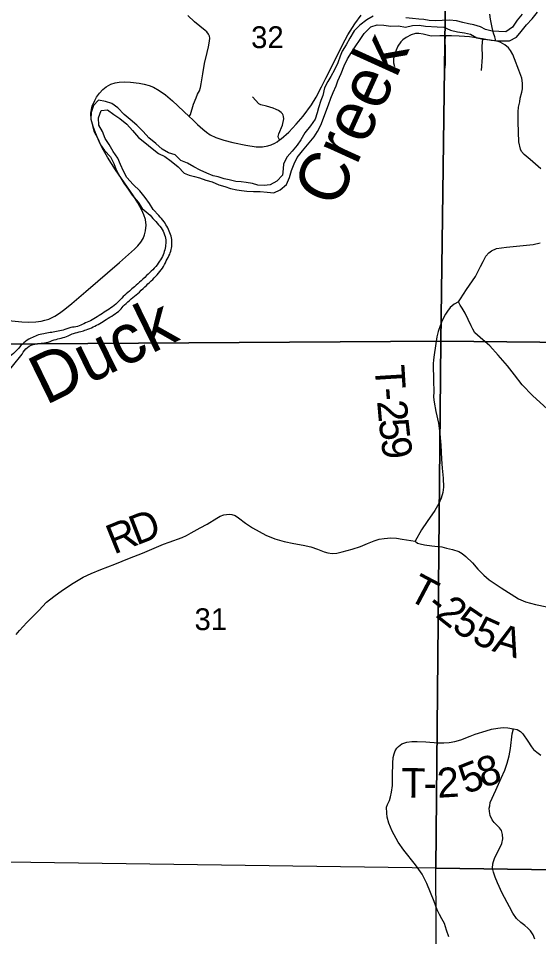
# Model space of a CAD drawing. Extents: x 0 to 34, y 0 to 22.
# Drawn here: x 6.533 to 7.529, y 17.691 to 19.45 of the extents above; entities that cross this region are included whole.
import ezdxf

# ---------------------------------------------------------------- set-up
doc = ezdxf.new("R2010")
doc.units = 0
for name, color, linetype in [('GM_X_Corporation', 7, 'Continuous'), ('GM_X_County_Road', 7, 'Continuous'), ('GM_X_Major_River', 7, 'Continuous'), ('GM_X_Major_River_Text', 7, 'Continuous'), ('GM_X_Section_Text', 7, 'Continuous'), ('GM_X_State_Route', 7, 'Continuous'), ('GM_X_Township_Road', 7, 'Continuous'), ('GM_X_Township_Road_Text', 7, 'Continuous')]:
    doc.layers.add(name, color=color, linetype=linetype)

msp = doc.modelspace()

# ---------------------------------------------------------------- linework, layer by layer
at = {"layer": 'GM_X_Corporation'}
for points in [[(7.3548, 19.8302), (7.3418, 18.8315), (6.4726, 18.8257), (6.4758, 19.3912), (6.4778, 19.8399)], [(8.3645, 19.8193), (8.353, 18.8213), (7.3418, 18.8315), (7.3548, 19.8302)], [(7.3418, 18.8315), (7.332, 17.8222), (6.4651, 17.8343), (6.4692, 18.391), (6.4726, 18.8257)], [(8.353, 18.8213), (8.3394, 17.8082), (7.332, 17.8222), (7.3418, 18.8315)], [(8.3394, 17.8082), (8.3265, 16.8592), (7.3376, 16.8759), (7.332, 17.8222)]]:
    msp.add_lwpolyline(points, close=True, dxfattribs=at)
at = {"layer": 'GM_X_County_Road'}
for points in [[(7.5332, 19.1614), (7.5129, 19.1793), (7.5011, 19.1892), (7.4959, 19.1947), (7.4939, 19.1994), (7.4912, 19.2136), (7.4896, 19.2512), (7.4899, 19.2707), (7.4906, 19.2797), (7.4926, 19.2898), (7.4936, 19.2971), (7.4965, 19.3081), (7.4983, 19.3146), (7.4981, 19.3257), (7.4969, 19.3355), (7.4912, 19.3508), (7.4827, 19.3724), (7.4795, 19.3808), (7.4753, 19.388), (7.4712, 19.3931), (7.4643, 19.3992), (7.4552, 19.4039), (7.4467, 19.4066), (7.4449, 19.4145), (7.4422, 19.4213), (7.4399, 19.4324), (7.4385, 19.4385), (7.4367, 19.4485), (7.4357, 19.4575)], [(7.5461, 18.7013), (7.517, 18.7276), (7.4975, 18.7477), (7.4824, 18.7671), (7.4695, 18.7842), (7.4517, 18.8049), (7.4358, 18.8224), (7.4265, 18.8301), (7.4171, 18.8384), (7.4119, 18.8431), (7.407, 18.8478), (7.4027, 18.8543), (7.3998, 18.861), (7.3943, 18.8729), (7.3885, 18.8851), (7.3823, 18.895), (7.379, 18.9006), (7.3756, 18.907), (7.3791, 18.9128), (7.391, 18.9306), (7.4082, 18.9553), (7.4179, 18.9745), (7.4226, 18.9843), (7.4278, 18.9943), (7.4337, 19.0008), (7.4388, 19.0045), (7.448, 19.0091), (7.4672, 19.0113), (7.5185, 19.0165), (7.5317, 19.0201)]]:
    msp.add_lwpolyline(points, dxfattribs=at)
at = {"layer": 'GM_X_Major_River'}
for points in [[(7.2123, 19.4537), (7.1999, 19.4467), (7.1867, 19.4367), (7.1759, 19.4256), (7.1673, 19.4119), (7.1603, 19.3993), (7.1532, 19.3871), (7.1492, 19.3772), (7.1444, 19.3646), (7.1381, 19.3512), (7.1314, 19.3383), (7.1255, 19.3287), (7.1192, 19.3165), (7.1159, 19.3021), (7.1122, 19.2926), (7.1075, 19.2785), (7.1053, 19.269), (7.1013, 19.2568), (7.0923, 19.2438), (7.0815, 19.2304), (7.0741, 19.2174), (7.067, 19.2071), (7.0569, 19.1956), (7.0476, 19.1846), (7.0409, 19.1712), (7.0403, 19.1613)], [(7.1057, 19.233), (7.112, 19.2452), (7.1172, 19.2585), (7.1216, 19.2707), (7.1267, 19.284), (7.1315, 19.2966), (7.1359, 19.3076), (7.1415, 19.3206), (7.1444, 19.3301), (7.1507, 19.3442), (7.1566, 19.3586), (7.1632, 19.3724), (7.171, 19.3842), (7.1788, 19.3972), (7.1859, 19.4075), (7.1949, 19.4205), (7.208, 19.4335), (7.2197, 19.4374), (7.2329, 19.4364), (7.2462, 19.4347), (7.2609, 19.4352), (7.2742, 19.4327), (7.2878, 19.4363), (7.3003, 19.4368), (7.3124, 19.4346), (7.3344, 19.4333), (7.3472, 19.4331), (7.3605, 19.4272), (7.3738, 19.4239), (7.3871, 19.4218), (7.3988, 19.4196), (7.4107, 19.4125), (7.4228, 19.41), (7.4361, 19.4083), (7.4482, 19.4065), (7.4603, 19.407), (7.4732, 19.4064), (7.4867, 19.4137), (7.4957, 19.4244), (7.5057, 19.4374), (7.5162, 19.4489), (7.527, 19.4619)], [(7.4972, 19.4578), (7.4875, 19.446), (7.4786, 19.4326), (7.4658, 19.4241), (7.4525, 19.4244), (7.44, 19.4254), (7.4271, 19.4286), (7.4176, 19.4335), (7.4051, 19.4375), (7.3948, 19.4393), (7.3838, 19.4418), (7.3717, 19.4451), (7.3584, 19.4461), (7.3444, 19.4456), (7.3316, 19.4451), (7.3191, 19.4457), (7.3092, 19.4475), (7.2994, 19.4485), (7.2873, 19.4492), (7.2748, 19.4509)], [(7.0403, 19.1613), (7.0389, 19.1496), (7.028, 19.1381), (7.0149, 19.1311), (7.0035, 19.1298), (6.9914, 19.1301), (6.9815, 19.1334), (6.969, 19.1352), (6.9596, 19.1366), (6.9497, 19.1376), (6.9368, 19.1405), (6.9273, 19.1423), (6.9156, 19.146), (6.9061, 19.1482), (6.8939, 19.1533), (6.881, 19.1593), (6.8688, 19.1652), (6.8566, 19.1723), (6.8444, 19.1778), (6.833, 19.1883), (6.8208, 19.1924), (6.8083, 19.1995), (6.796, 19.2103), (6.783, 19.2212), (6.7723, 19.2332), (6.7597, 19.2452), (6.7471, 19.2561), (6.7356, 19.2658), (6.7234, 19.2782), (6.7123, 19.2868), (6.6998, 19.2908), (6.6865, 19.293), (6.6768, 19.2826), (6.6728, 19.2697), (6.6718, 19.2575), (6.6749, 19.2447), (6.6785, 19.2326), (6.6854, 19.2198), (6.6905, 19.2073), (6.6978, 19.1964), (6.7093, 19.1848), (6.7158, 19.1719), (6.7205, 19.1595), (6.7271, 19.1466), (6.7348, 19.1342), (6.7432, 19.1229), (6.7509, 19.1109), (6.7624, 19.0977), (6.7701, 19.0857), (6.7856, 19.0726)], [(6.8019, 19.0722), (6.7911, 19.0837), (6.7844, 19.0949), (6.776, 19.107), (6.766, 19.1197), (6.753, 19.1317), (6.7411, 19.1449), (6.7342, 19.1573), (6.7287, 19.1698), (6.7237, 19.1819), (6.7145, 19.195), (6.7067, 19.2079), (6.6994, 19.2199), (6.694, 19.2328), (6.687, 19.2452), (6.6865, 19.2592), (6.6917, 19.2733), (6.7041, 19.2746), (6.716, 19.2656), (6.7274, 19.2581), (6.7411, 19.2473), (6.7519, 19.2349), (6.7634, 19.2217), (6.7752, 19.212), (6.7893, 19.2008), (6.8015, 19.191), (6.8137, 19.1855), (6.8259, 19.1765), (6.8393, 19.1653), (6.8508, 19.1533), (6.8603, 19.1492), (6.8701, 19.147), (6.8796, 19.1441), (6.8922, 19.14), (6.9039, 19.1368), (6.9169, 19.1312), (6.9286, 19.1279), (6.9389, 19.1242), (6.951, 19.1213), (6.9605, 19.1199), (6.9707, 19.1189), (6.9832, 19.1179), (6.9961, 19.118), (7.0093, 19.117), (7.0222, 19.1156), (7.0343, 19.1215), (7.0466, 19.1314), (7.0522, 19.1448), (7.0562, 19.1585), (7.061, 19.171), (7.0669, 19.1832), (7.077, 19.1962), (7.0994, 19.223), (7.1057, 19.233)]]:
    msp.add_lwpolyline(points, dxfattribs=at)
for points in [[(6.7856, 19.0726), (6.796, 19.0607), (6.8065, 19.0483), (6.8132, 19.0355), (6.8153, 19.0219), (6.814, 19.0097), (6.8104, 18.9971), (6.8034, 18.9845), (6.7934, 18.9714), (6.7815, 18.9602), (6.7684, 18.9474), (6.7553, 18.9358), (6.7456, 18.9272), (6.734, 18.9168), (6.7225, 18.9052), (6.7105, 18.8951), (6.6974, 18.8869), (6.6843, 18.8783), (6.6711, 18.8705), (6.6587, 18.865), (6.6463, 18.8598), (6.6334, 18.8577), (6.6187, 18.8529), (6.6059, 18.85), (6.5941, 18.8479), (6.5817, 18.8458), (6.5688, 18.8425), (6.5571, 18.8374), (6.5436, 18.8284), (6.5332, 18.8176), (6.5209, 18.8052), (6.5082, 18.7948), (6.4951, 18.7824), (6.4831, 18.7738), (6.4699, 18.7728), (6.4573, 18.776), (6.4436, 18.7781), (6.4306, 18.7832), (6.418, 18.7905), (6.4054, 18.796), (6.3927, 18.8042), (6.3812, 18.8112), (6.369, 18.8163), (6.3557, 18.8179), (6.3462, 18.8182), (6.3329, 18.8202), (6.3184, 18.8219), (6.304, 18.8246), (6.291, 18.829), (6.2792, 18.8307), (6.2671, 18.832), (6.2553, 18.8295), (6.2456, 18.8248), (6.2343, 18.8193), (6.2227, 18.8092), (6.2142, 18.7973), (6.2064, 18.7876), (6.1979, 18.7738), (6.1928, 18.7604), (6.1877, 18.7501), (6.1845, 18.7379), (6.1851, 18.7242), (6.188, 18.7117), (6.192, 18.6993), (6.1941, 18.6879), (6.1966, 18.6739), (6.1987, 18.6603), (6.2035, 18.6471), (6.2098, 18.6342), (6.2153, 18.6211), (6.2197, 18.6082), (6.2241, 18.5961), (6.2285, 18.5833), (6.2291, 18.5712), (6.2335, 18.5587), (6.2386, 18.5466), (6.2453, 18.5342), (6.2505, 18.5222), (6.2609, 18.5098), (6.2732, 18.4986), (6.2814, 18.4866), (6.2919, 18.4727), (6.2963, 18.4603), (6.2984, 18.4485), (6.302, 18.4372), (6.3011, 18.4231), (6.2968, 18.4102), (6.2909, 18.3975), (6.2813, 18.3856), (6.2693, 18.3759), (6.2566, 18.3669), (6.2434, 18.3595), (6.231, 18.3524), (6.2163, 18.3465), (6.2032, 18.3405), (6.1885, 18.3331), (6.1753, 18.3291)], [(6.2087, 18.3296), (6.2215, 18.3352), (6.2331, 18.3395), (6.2433, 18.3447), (6.255, 18.3502), (6.2685, 18.3569), (6.2809, 18.3624), (6.2932, 18.374), (6.3018, 18.3859), (6.3099, 18.3986), (6.3153, 18.4139), (6.3177, 18.4261), (6.319, 18.4386), (6.3177, 18.4489), (6.3133, 18.4625), (6.3071, 18.4738), (6.2996, 18.4858), (6.2926, 18.4978), (6.2826, 18.5071), (6.2718, 18.5183), (6.2606, 18.5299), (6.2554, 18.542), (6.2503, 18.5537), (6.2467, 18.5661), (6.2431, 18.5767), (6.2406, 18.5892), (6.2365, 18.6039), (6.2318, 18.6156), (6.2262, 18.6288), (6.2214, 18.6417), (6.2174, 18.6537), (6.2142, 18.6639), (6.2094, 18.6768), (6.2074, 18.687), (6.2045, 18.6991), (6.2028, 18.7089), (6.2011, 18.7211), (6.2012, 18.7347), (6.2018, 18.7473), (6.2057, 18.7595), (6.2108, 18.7725), (6.2193, 18.786), (6.2282, 18.7979), (6.2394, 18.8083), (6.2518, 18.8154), (6.2635, 18.8186), (6.2764, 18.8173), (6.2882, 18.8134), (6.302, 18.8083), (6.3142, 18.8047), (6.3275, 18.8023), (6.3378, 18.8017), (6.351, 18.8011), (6.3647, 18.7983), (6.375, 18.797), (6.3884, 18.7927), (6.4006, 18.7861), (6.4125, 18.7798), (6.424, 18.7728), (6.4359, 18.7662), (6.4496, 18.7611), (6.4633, 18.7571), (6.4766, 18.7593), (6.4905, 18.7633), (6.5037, 18.7677), (6.5168, 18.7774), (6.5272, 18.7902), (6.538, 18.8036), (6.5476, 18.8167), (6.5615, 18.8253), (6.5865, 18.8288), (6.602, 18.834), (6.6152, 18.8376), (6.6288, 18.842), (6.6389, 18.8464), (6.6529, 18.8501), (6.6631, 18.8533), (6.6763, 18.8588), (6.689, 18.8655), (6.7014, 18.8733), (6.7153, 18.8819), (6.7277, 18.8912), (6.7362, 18.9009), (6.7493, 18.9125), (6.7616, 18.9226), (6.7751, 18.9354), (6.7874, 18.947), (6.7989, 18.9589), (6.809, 18.9716), (6.8163, 18.9851), (6.8229, 18.9981), (6.8265, 19.0099), (6.827, 19.0228), (6.8245, 19.0357), (6.819, 19.0485), (6.812, 19.0602), (6.8019, 19.0722)]]:
    msp.add_spline(points, degree=3, dxfattribs=at)
at = {"layer": 'GM_X_State_Route'}
for points in [[(6.6445, 18.9114), (6.6626, 18.9269), (6.7265, 18.9821), (6.7554, 19.0079), (6.7616, 19.0141), (6.7673, 19.0209), (6.7719, 19.0283), (6.7748, 19.0351), (6.7768, 19.0427), (6.7778, 19.0537), (6.7763, 19.0645), (6.7736, 19.0733), (6.7696, 19.0826), (6.7617, 19.0966), (6.7535, 19.1099), (6.7194, 19.1597), (6.7036, 19.1841), (6.6937, 19.2019), (6.6878, 19.2139), (6.6807, 19.2304), (6.6763, 19.2429), (6.6726, 19.2562), (6.6718, 19.2683), (6.6742, 19.2813), (6.6793, 19.2924), (6.6828, 19.2986), (6.6887, 19.3067), (6.6949, 19.3133), (6.7015, 19.3188), (6.71, 19.3237), (6.7184, 19.3263), (6.7259, 19.3275), (6.7361, 19.3282), (6.748, 19.3277), (6.7647, 19.3258), (6.7742, 19.3238), (6.7836, 19.3213), (6.7921, 19.3177), (6.8025, 19.3119), (6.8145, 19.3033), (6.8284, 19.2917), (6.8604, 19.2621), (6.8669, 19.2553), (6.8758, 19.2465), (6.886, 19.2373), (6.8933, 19.2315), (6.9003, 19.227), (6.9109, 19.2218), (6.9264, 19.2165), (6.9438, 19.2123), (6.9688, 19.2069), (6.9885, 19.2039), (7.0004, 19.2039), (7.0105, 19.2054), (7.017, 19.2078), (7.0239, 19.2109), (7.0288, 19.2136), (7.033, 19.2169), (7.0361, 19.219), (7.0508, 19.232), (7.065, 19.247), (7.078, 19.2625), (7.0941, 19.2843), (7.1032, 19.2991), (7.1132, 19.3184), (7.1215, 19.3353), (7.1464, 19.3845), (7.1533, 19.3988), (7.1635, 19.418), (7.1773, 19.4395), (7.1895, 19.4558)], [(6.4294, 18.8794), (6.4769, 18.875), (6.5206, 18.8703), (6.5396, 18.8686), (6.5528, 18.868), (6.5664, 18.8683), (6.5769, 18.8698), (6.5838, 18.8715), (6.5915, 18.874), (6.6029, 18.8796), (6.6119, 18.8851), (6.6219, 18.8926), (6.6354, 18.9036), (6.6445, 18.9114)]]:
    msp.add_lwpolyline(points, dxfattribs=at)
at = {"layer": 'GM_X_Township_Road'}
for points in [[(6.8604, 19.2621), (6.8628, 19.2654), (6.8683, 19.2857), (6.8732, 19.2976), (6.8763, 19.3046), (6.8797, 19.3112), (6.8819, 19.3173), (6.8831, 19.3243), (6.8865, 19.3434), (6.8895, 19.3636), (6.8945, 19.3844), (6.8973, 19.3955), (6.8993, 19.4063), (6.8997, 19.4121), (6.8991, 19.4156), (6.8974, 19.4196), (6.8939, 19.424), (6.8907, 19.4268), (6.8704, 19.4431), (6.8577, 19.4552)], [(7.4467, 19.4066), (7.4383, 19.4076), (7.4279, 19.4092), (7.4213, 19.4105), (7.3967, 19.4145), (7.3873, 19.4153), (7.377, 19.4156), (7.3622, 19.4164), (7.3506, 19.4163), (7.3396, 19.416), (7.3234, 19.4156), (7.3079, 19.4196), (7.2998, 19.4209), (7.2931, 19.4206), (7.285, 19.4182), (7.2752, 19.4132), (7.269, 19.4085), (7.2649, 19.4048), (7.2593, 19.3962), (7.2562, 19.3886), (7.252, 19.3769), (7.251, 19.3711), (7.251, 19.3643), (7.2533, 19.3576)], [(7.3506, 19.4163), (7.3494, 19.4083), (7.3499, 19.3908), (7.3501, 19.3754), (7.3499, 19.3612), (7.3487, 19.3518)], [(7.4213, 19.4105), (7.4204, 19.3965), (7.4206, 19.3751), (7.4192, 19.3497)], [(7.033, 19.2169), (7.0309, 19.2208), (7.0301, 19.2235), (7.0318, 19.2287), (7.0388, 19.2449), (7.0411, 19.2575), (7.0408, 19.2616), (7.0399, 19.2645), (7.0389, 19.2669), (7.0361, 19.2697), (7.0309, 19.2734), (7.0263, 19.2753), (7.0207, 19.2778), (7.008, 19.2815), (6.9972, 19.2842), (6.9935, 19.286), (6.9815, 19.2994)], [(7.3756, 18.907), (7.3671, 18.9022), (7.3598, 18.8959), (7.3546, 18.8893), (7.3505, 18.8833), (7.3443, 18.8711), (7.3403, 18.8611), (7.3367, 18.85), (7.3339, 18.84), (7.3288, 18.8053), (7.3275, 18.7959), (7.3272, 18.7881), (7.3278, 18.7559), (7.3281, 18.7349), (7.3278, 18.7243), (7.329, 18.7147), (7.3324, 18.6966), (7.337, 18.6748), (7.3401, 18.6543), (7.3418, 18.6326), (7.3432, 18.6057), (7.3442, 18.5881), (7.3464, 18.569), (7.3466, 18.552), (7.3455, 18.5419), (7.3426, 18.5307), (7.3377, 18.5208), (7.33, 18.5075), (7.3157, 18.4862), (7.3047, 18.4704), (7.2923, 18.4483)], [(6.5293, 18.2701), (6.5354, 18.2774), (6.5493, 18.2929), (6.5723, 18.3157), (6.5869, 18.3316), (6.601, 18.3429), (6.6177, 18.3549), (6.6378, 18.3682), (6.6571, 18.3794), (6.6723, 18.3867), (6.6909, 18.3943), (6.7181, 18.4048), (6.7459, 18.4162), (6.7706, 18.4254), (6.7845, 18.4313), (6.811, 18.4428), (6.8216, 18.4468), (6.8465, 18.4558), (6.8552, 18.4594), (6.8639, 18.4643), (6.8811, 18.4739), (6.8945, 18.4814), (6.913, 18.4929), (6.9195, 18.4965), (6.9262, 18.4989), (6.9367, 18.5003), (6.9419, 18.4997), (6.9482, 18.4975), (6.9548, 18.4933), (6.9677, 18.4832), (6.9813, 18.474), (7.0069, 18.4603), (7.0241, 18.4533), (7.0416, 18.448), (7.0606, 18.4441), (7.0782, 18.4409), (7.0927, 18.4376), (7.1054, 18.433), (7.1183, 18.4281), (7.1252, 18.426), (7.1335, 18.4247), (7.143, 18.4259), (7.153, 18.428), (7.1721, 18.4334), (7.1877, 18.4384), (7.2012, 18.4442), (7.2144, 18.4494), (7.2235, 18.4522), (7.2333, 18.4536), (7.2461, 18.4549), (7.2566, 18.4544), (7.2676, 18.4527), (7.2923, 18.4483)], [(7.2923, 18.4483), (7.2972, 18.4449), (7.302, 18.4433), (7.3106, 18.4415), (7.3242, 18.4397), (7.3361, 18.4387), (7.3437, 18.4379), (7.3528, 18.4355), (7.3641, 18.4325), (7.376, 18.4286), (7.3827, 18.4249), (7.3897, 18.4191), (7.4021, 18.4074), (7.4128, 18.3951), (7.4239, 18.3833), (7.4339, 18.3748), (7.4569, 18.3591), (7.4906, 18.3383), (7.504, 18.3324), (7.5228, 18.3273), (7.5444, 18.3226)], [(7.238, 17.9395), (7.2398, 17.9444), (7.2434, 17.9523), (7.2457, 17.9591), (7.2475, 17.9681), (7.249, 17.981), (7.2491, 17.9996), (7.2496, 18.0233), (7.2507, 18.0344), (7.2521, 18.0413), (7.2541, 18.0469), (7.2574, 18.0525), (7.2609, 18.0555), (7.2671, 18.0604), (7.2769, 18.0636), (7.2865, 18.0648), (7.2962, 18.0652), (7.3133, 18.0643), (7.3364, 18.0623), (7.3474, 18.0623), (7.3577, 18.0628), (7.3688, 18.065), (7.3801, 18.0684), (7.398, 18.0755), (7.4075, 18.079), (7.4282, 18.0854), (7.4387, 18.0885), (7.4506, 18.0905), (7.4607, 18.0915), (7.4701, 18.0911), (7.4806, 18.0895)], [(7.5213, 17.6865), (7.5187, 17.6949), (7.5135, 17.7023), (7.5081, 17.7076), (7.5023, 17.7128), (7.4951, 17.7187), (7.4866, 17.7263), (7.4795, 17.736), (7.4734, 17.7482), (7.4593, 17.7745), (7.4502, 17.7941), (7.4454, 17.8051), (7.4424, 17.8145), (7.4408, 17.8227), (7.4415, 17.8305), (7.4427, 17.8352), (7.4452, 17.8428), (7.4527, 17.8575), (7.4582, 17.8696), (7.4603, 17.8789), (7.4596, 17.8872), (7.4577, 17.8947), (7.4538, 17.8999), (7.4493, 17.9042), (7.4438, 17.91), (7.44, 17.9152), (7.4363, 17.9232), (7.4355, 17.927), (7.4348, 17.9307), (7.4344, 17.9374), (7.4352, 17.9418), (7.4364, 17.948), (7.4468, 17.972), (7.457, 17.9949), (7.4639, 18.0098), (7.4688, 18.0236), (7.4728, 18.0375), (7.4752, 18.0518), (7.4781, 18.0797), (7.4806, 18.0895), (7.4876, 18.0877), (7.4945, 18.084), (7.4987, 18.0797), (7.5079, 18.0656), (7.5153, 18.0549), (7.5191, 18.0499), (7.5257, 18.0444), (7.5331, 18.0388)], [(7.3568, 17.6909), (7.3528, 17.7037), (7.3488, 17.7164), (7.3434, 17.7256), (7.3394, 17.7335), (7.3349, 17.7428), (7.3289, 17.7584), (7.3148, 17.793), (7.3057, 17.8108), (7.2933, 17.8285), (7.2709, 17.8567), (7.2603, 17.8721), (7.2486, 17.8935), (7.2424, 17.9087), (7.239, 17.9198), (7.2381, 17.9277), (7.238, 17.9395)]]:
    msp.add_lwpolyline(points, dxfattribs=at)

# ---------------------------------------------------------------- texts
at = {"layer": 'GM_X_Major_River_Text'}
for s, height, rotation, p in [('Creek', 0.09468, 65.5354, (7.1424, 19.0836)), ('Duck', 0.09469, 26.0356, (6.5853, 18.7083))]:
    msp.add_text(s, height=height, rotation=rotation, dxfattribs=at).set_placement(p)
at = {"layer": 'GM_X_Section_Text'}
for s, p in [('32', (6.9787, 19.3927)), ('31', (6.8704, 18.2782))]:
    msp.add_text(s, height=0.04186, rotation=0, dxfattribs=at).set_placement(p)
at = {"layer": 'GM_X_Township_Road_Text'}
for s, rotation, p in [('T', 273.482, (7.2152, 18.7843)), ('-', 273.9888, (7.2179, 18.7413)), ('2', 275.1301, (7.2196, 18.7168)), ('5', 276.2203, (7.2228, 18.6808)), ('9', 277.435, (7.2268, 18.6447)), ('D', 21.2352, (6.7592, 18.44)), ('R', 22.0797, (6.7161, 18.4226)), ('T', 332.1143, (7.2757, 18.3383)), ('2', 321.4481, (7.3293, 18.3053)), ('-', 321.2829, (7.3109, 18.32)), ('5', 325.7646, (7.3604, 18.2807)), ('5', 335.7528, (7.3988, 18.2557)), ('A', 343.1356, (7.4382, 18.2386)), ('5', 21.5601, (7.39, 17.9634)), ('8', 17.594, (7.4216, 17.9759)), ('T', 359.49, (7.2659, 17.9574)), ('2', 3.4076, (7.336, 17.9571)), ('-', 359.8563, (7.3088, 17.957))]:
    msp.add_text(s, height=0.0568, rotation=rotation, dxfattribs=at).set_placement(p)

doc.saveas('drawing.dxf')
